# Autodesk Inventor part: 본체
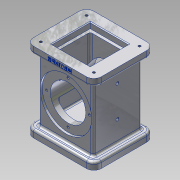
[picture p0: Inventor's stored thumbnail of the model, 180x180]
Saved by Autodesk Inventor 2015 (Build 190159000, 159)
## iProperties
Created: 2017-08
Part Number: 본체
Material: 알루미늄 6061
Document SubType Name: Modeling
Designer: Administrator
Mass: 868.441 g
Surface Area: 643.29 cm^2
Volume: 321.645 cm^3
Density: 2.7 g/cm^3
Appearance: 알루미늄 - 평지
Author: Administrator
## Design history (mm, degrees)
sketch "스케치1"
  geometry: L1 (41, 46)-(-41, 46); L2 (-41, 46)-(-41, -46); L3 (-41, -46)-(41, -46); L4 (41, -46)-(41, 46); 3 further points
  constraints: 8 end point, 2 midpoint, 2 parallel, 1 horizontal, 1 horizontal alignment, 1 perpendicular, 1 vertical alignment
  dimensions: "d0" = 92 distance of L3.end L1.start; "d1" = 82 distance of L2.end L3.end
extrude "돌출1" new body sketch "스케치1" distance "d2" = 108; taper "d3" = 0 deg
node "작업 평면1"
sketch "스케치2"
  geometry: L1 (33, 37)-(-33, 37); L2 (-33, 37)-(-33, -37); L3 (-33, -37)-(33, -37); L4 (33, -37)-(33, 37); L5 (58.021, 66.542)-(-62.586, 66.542); L6 (-62.586, 66.542)-(-62.586, -75.451); L7 (-62.586, -75.451)-(58.021, -75.451); L8 (58.021, -75.451)-(58.021, 66.542); 3 further points
  constraints: 16 end point, 4 parallel, 2 horizontal, 2 midpoint, 2 perpendicular, 1 horizontal alignment, 1 vertical alignment
  dimensions: "d5" = 74 distance of L3.end L1.start; "d6" = 66 distance of L2.end L3.end
extrude "돌출2" cut sketch "스케치2" distance "d7" = 88; taper "d8" = 0 deg
sketch "스케치3"
  geometry: L1 (-33, 10)-(-33, 98) reference; L2 (-33, 89)-(-30, 89); L3 (-30, 89)-(-30, 54); L4 (-30, 54)-(-33, 54); L5 (-33, 54)-(-33, 89); L6 (-30, 54)-(30, 54); L7 (30, 54)-(30, 78); L8 (30, 78)-(-30, 78); L9 (-30, 78)-(-30, 54); L10 (33, 10)-(33, 98) reference; L11 (30, 54)-(33, 54); L12 (33, 54)-(33, 89); L13 (33, 89)-(30, 89); L14 (30, 89)-(30, 54); L15 (-41, 0)-(41, 0) reference; L16 (41, 108)-(-41, 108) reference; L17 (-26, 108)-(26, 108); L18 (26, 108)-(26, 100); L19 (26, 100)-(-26, 100); L20 (-26, 100)-(-26, 108); L21 (41, 0)-(-41, 0) reference; L22 (-24, 0)-(24, 0); L23 (24, 0)-(24, 16); L24 (24, 16)-(-24, 16); L25 (-24, 16)-(-24, 0); L26 (-22, 100)-(22, 100); L27 (22, 100)-(22, 26); L28 (22, 26)-(-22, 26); L29 (-22, 26)-(-22, 100); 7 further points
  constraints: 48 end point, 12 parallel, 6 horizontal, 6 midpoint, 6 perpendicular, 5 point on line, 2 vertical alignment, 1 coincident
  dimensions: "d9" = 54 distance from line of L15 L4.end; "d10" = 70 diameter of L2 L6; "d11" = 70 diameter of L13 L11; "d12" = 48 diameter of L8 L6; "d13" = 3 distance of L2.start L2.end; "d14" = 3 distance of L12.end L13.end; "d15" = 52 distance of L17.start L17.end; "d16" = 8 distance of L17.end L18.end; "d17" = 16 distance of L22.end L23.end; "d18" = 48 distance of L22.start L22.end; "d19" = 44 distance of L27.end L28.end; "d20" = 74 distance of L28.end L26.start
extrude "돌출3" cut sketch "스케치3" stored distance "d21" = 52; taper "d22" = 0 deg
extrude "돌출4" cut sketch "스케치3" stored distance "d23" = 44; taper "d24" = 0 deg
revolve "회전1" stored, may be unused: angle "d25" = 90 deg
extrude "돌출5" cut sketch "스케치3" stored distance "d26" = 48; taper "d27" = 0 deg
sketch "스케치4" dims "d28" = 58
  geometry: 3 further points
  constraints: 1 vertical alignment, 2 other
hole "구멍1" sketch "스케치4" at (0, 29) diameter "d29" = 3.242; stored, may be unused: countersink angle "d33" = 90 deg, drill point angle "d35" = 118 deg; dims "d30" = 4, "d31" = 4, "d32" = 2, "d34" = 6
sketch "스케치5"
  geometry: L1 (33, -10)-(33, 28); L2 (33, 28)-(33, 70); L3 (0, 0)-(0, 88) reference; 2 further points
  constraints: 4 end point, 2 coincident, 1 point on line, 1 vertical
  dimensions: "d39" = 38 distance of L1.start L1.end; "d40" = 42 distance of L1.end L2.end; "d41" = 33 distance between parallel lines of L3 L2 (derived)
hole "구멍2" sketch "스케치5" at (33, 28), (33, 70) diameter "d42" = 4.134; stored, may be unused: countersink angle "d46" = 90 deg, drill point angle "d48" = 118 deg; dims "d43" = 10, "d44" = 4, "d45" = 2, "d47" = 20
sketch "스케치6"
  geometry: L1 (0, 0)-(92, 0) reference; L2 (0, -10)-(0, 0) reference; 2 further points
  constraints: 1 other
  dimensions: "d49" = 4 distance from line of L1 point (46, -4); "d50" = 46 distance from line of L2 point (46, -4)
fillet "모깎기1" dims "d51" = 10
fillet "모깎기2" dims "d52" = 3
chamfer "모따기1" distance "d53" = 1; stored, may be unused: second distance "d54" = 2, angle "d55" = 45 deg
feature "엠보싱1" dims "d0" = 92, "d1" = 82, "d56" = 0.5, "d57" = 0
fillet "모깎기3" dims "d58" = 3
sketch "스케치7"
  geometry: A1 r 10 centre (31, 36) between (41, 36) and (31, 46) reference; 2 further points
  constraints: 1 coincident
hole "구멍3" sketch "스케치7" at (31, 36) diameter "d59" = 3.242; stored, may be unused: countersink angle "d63" = 90 deg, drill point angle "d65" = 118 deg; dims "d60" = 4, "d61" = 4, "d62" = 2, "d64" = 6
sketch "스케치8"
  geometry: A1 r 10 centre (-31, -36) between (-41, -36) and (-31, -46) reference; 2 further points
  constraints: 1 coincident
hole "구멍4" sketch "스케치8" at (-31, -36) diameter "d66" = 3.242; stored, may be unused: countersink angle "d70" = 90 deg, drill point angle "d72" = 118 deg; dims "d67" = 4, "d68" = 4, "d69" = 2, "d71" = 6
fillet "모깎기4" dims "d73" = 2
node "솔리드1"
pattern_circular "원형 패턴1" dims angle "d37" = 360 deg
mirror "대칭1"
mirror "대칭2"
mirror "대칭3"
mirror "대칭4"
mirror "대칭5"
